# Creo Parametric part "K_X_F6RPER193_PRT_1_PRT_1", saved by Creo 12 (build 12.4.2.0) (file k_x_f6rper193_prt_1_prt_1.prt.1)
Units: Custom; MM, KILOGRAM, SECS

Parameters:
  PTC_WM_ITERATION = "0"
  PTC_WM_VERSION = "-.0"
  PTC_WM_LIFECYCLE_STATE = "In Work"
  PTC_WM_LIFECYCLE = "MO_CADDocument"
  PTC_WM_CREATED_BY = "Maximilian Roepper (Z0017RMS: MO)"
  PTC_WM_CREATED_ON = "18-Sep-26 11:36:42 AM"
  PTC_WM_MODIFIED_BY = "Maximilian Roepper (Z0017RMS: MO)"
  PTC_WM_MODIFIED_ON = "18-Sep-26 11:36:46 AM"
  PDMLINKNUMBER = "PDM000071455216"
  PTC_WM_NAME = "k_x_f6rper193_prt_1_prt_1.prt"
  PTC_WM_NUMBER = "PDM000071455216"

Other parameters: WEIGHT, WEIGHT_FACTOR, WEIGHT_ADD, _MASS_TEMP, _DIFF_TEMP, MC_ERRORS, SUPPLIER

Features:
  1. coordinate system
  2. datum plane "PRT_YZ"
  3. datum plane "PRT_XY"
  4. datum plane "PRT_XZ"
  5. coordinate system
  6. datum axis
  7. datum axis
  8. datum axis
  9. coordinate system
  10. imported feature
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
Other named items: PRT, SIEMENS_MO, DRW_VIEW_ORG, PRT_X, PRT_Y, PRT_Z, CS0, ROUGH_GROB

Layers: 00_STD_CSYS-KSYS, 01_STD_PLANES-EBENEN, 02_STD_AXES-ACHSEN, 03_STD_CSYS-KSYS, 24_IMPORT_FEAT-IMPORT_KE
